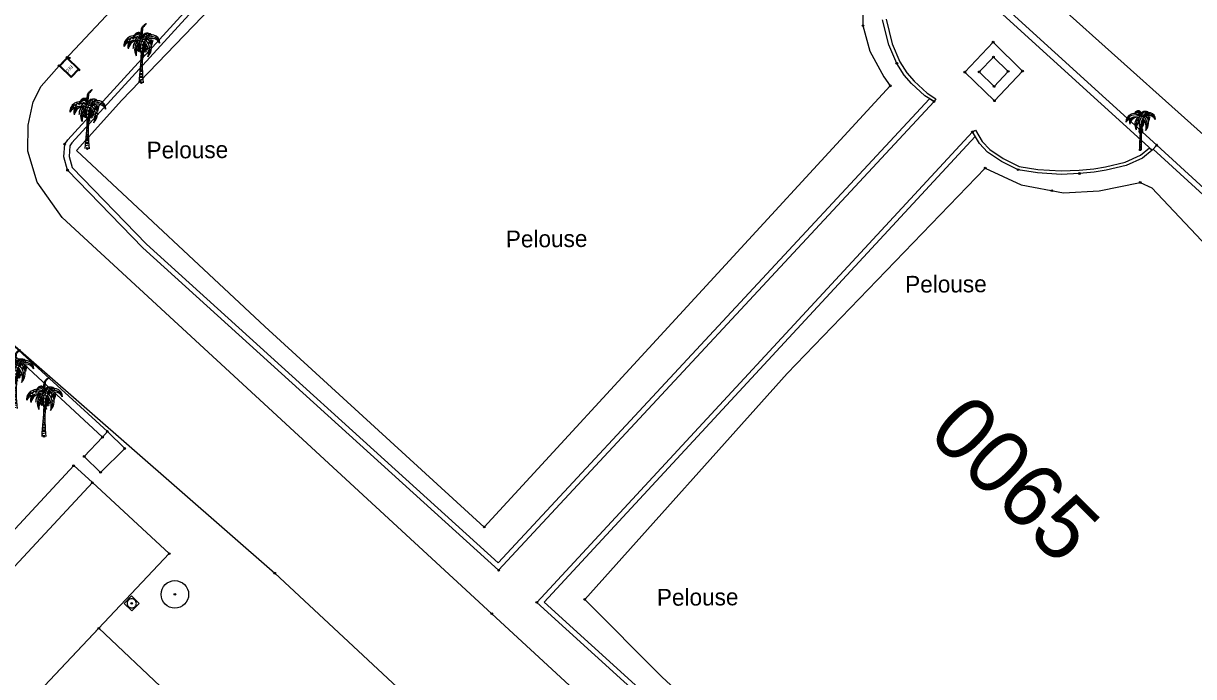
# Model space of a CAD drawing. Extents: x 344013 to 344423, y 298505 to 298795.
# Drawn here: x 344064.6 to 344132.3, y 298653.3 to 298691.1 of the extents above; entities that cross this region are included whole.
import ezdxf

# ---------------------------------------------------------------- set-up
doc = ezdxf.new("R2010")
doc.units = 0
for name, color, linetype in [('Default', 7, 'Continuous'), ('DH_CADRE -CARTOUCHE', 7, 'Continuous'), ('PC_CONCRETE', 7, 'Continuous'), ('PS_BOLT', 7, 'Continuous'), ('PS_CONST', 7, 'Continuous'), ('PS_HIDDEN', 7, 'Continuous'), ('RES_ELECTRICITE', 7, 'Continuous'), ('TOPO_POINT', 7, 'Continuous'), ('VOIRIE_BORDURE', 7, 'Continuous'), ('VOIRIE_ESPACE VERT', 7, 'Continuous')]:
    doc.layers.add(name, color=color, linetype=linetype)

# ---------------------------------------------------------------- blocks, each defined once
blk = doc.blocks.new('REG_INC')
at = {"layer": 'Default'}
for p, q in [((0, 1), (1, 1)), ((0, 0), (0, 1)), ((1, 0), (0, 0)), ((1, 1), (1, 0))]:
    blk.add_line(p, q, dxfattribs=at)
for start, end in [(135.0055, 180.0055), (180.0066, 225.0066), (90.0058, 135.0058), (225.0069, 270.0069), (45.0069, 90.0069), (270.0058, 315.0058), (0.0066, 45.0066), (315.0055, 0.0055)]:
    blk.add_arc((0.5, 0.5), 0.44, start, end, dxfattribs=at)
blk = doc.blocks.new('RES_ELECTRICITE')
at = {"layer": 'RES_ELECTRICITE'}
for points in [[(0, 0), (0, 1), (1, 1), (1, 0)], [(0.05, 0.05), (0.05, 0.95), (0.95, 0.95), (0.95, 0.05)]]:
    blk.add_lwpolyline(points, close=True, dxfattribs=at)
blk.add_text('EEC', height=0.2, dxfattribs=at).set_placement((0.237, 0.46))
blk = doc.blocks.new('POINT_DISPLAY')
at = {"layer": 'Default'}
blk.add_circle((0, 0), 0.05, dxfattribs=at)
blk = doc.blocks.new('COCO')
at = {"layer": 'Default'}
for p, q in [((-0.046, 0.891), (0.052, 0.927)), ((0.054, 0.998), (-0.041, 0.985)), ((-0.037, 1.06), (0.056, 1.071)), ((0.058, 1.14), (-0.03, 1.162)), ((-0.026, 1.226), (0.061, 1.212)), ((0.046, 0.033), (-0.076, 0.051)), ((-0.073, 0.17), (0.045, 0.209)), ((0.045, 0.292), (-0.07, 0.288)), ((-0.068, 0.371), (0.045, 0.374)), ((0.045, 0.47), (-0.065, 0.453)), ((-0.062, 0.537), (0.046, 0.552)), ((0.047, 0.655), (-0.058, 0.642))]:
    blk.add_line(p, q, dxfattribs=at)
for points in [[(0.029, 2.551), (-0.016, 2.896), (0.002, 3.125), (0.059, 3.241), (0.173, 3.348), (0.189, 3.356), (0.282, 3.415), (0.266, 3.373), (0.2, 3.318), (0.143, 3.247), (0.093, 3.2), (0.081, 3.165), (0.057, 3.133), (0.057, 3.099), (0.06, 3.037), (0.039, 2.989), (0.039, 2.944), (0.049, 2.877), (0.037, 2.841), (0.013, 2.736)], [(0.013, 2.736), (0.036, 2.813), (0.046, 2.746)], [(0.196, 2.687), (0.323, 2.715)], [(0.283, 2.765), (0.331, 2.786)], [(-0.746, 2.559), (-0.864, 2.483)], [(-0.77, 2.413), (-0.836, 2.333)], [(-0.607, 2.534), (-0.704, 2.443)], [(-0.636, 2.639), (-0.541, 2.608)], [(-0.421, 2.58), (-0.503, 2.523)], [(-0.487, 2.68), (-0.386, 2.65)], [(-0.183, 2.493), (-0.348, 2.417), (-0.401, 2.307), (-0.448, 2.203), (-0.471, 2.086), (-0.474, 2.023), (-0.466, 1.973), (-0.455, 2.054), (-0.451, 2.146), (-0.387, 2.292), (-0.351, 2.354), (-0.284, 2.404), (-0.233, 2.445), (-0.012, 2.495)], [(-0.256, 2.553), (-0.385, 2.508)], [(-0.276, 2.151), (-0.329, 2.086)], [(-0.203, 2.314), (-0.274, 2.258)], [(-0.23, 2.152), (-0.237, 2.043)], [(-0.161, 2.218), (-0.158, 2.122)], [(-0.04, 2.247), (-0.081, 2.179)], [(0.015, 2.414), (-0.056, 2.352)], [(-0.025, 2.032), (0.002, 1.954)], [(0.022, 2.24), (0.043, 2.13)], [(0.081, 2.404), (0.106, 2.299)], [(0.133, 2.608), (0.185, 2.634)], [(0.385, 2.37), (0.469, 2.254)], [(0.473, 2.115), (0.509, 2.012)], [(-0.321, 1.997), (-0.364, 1.9)], [(-0.059, 2.024), (-0.083, 1.998)], [(-0.055, 0.716), (0.048, 0.717), (0.049, 0.787), (-0.051, 0.795)]]:
    blk.add_lwpolyline(points, dxfattribs=at)
for centre, radius in [((-0.144, 1.978), 0.0616), ((-0.187, 1.897), 0.0384), ((-0.124, 1.896), 0.0376), ((-0.11, 1.84), 0.0471), ((0.134, 1.862), 0.0549), ((0.208, 1.822), 0.0626), ((0.254, 1.938), 0.0628)]:
    blk.add_circle(centre, radius, dxfattribs=at)
for centre, radius, start, end in [((-0.427, 2.113), 0.595, 43.61211, 181.46245), ((-0.123, 2.59), 0.323, 122.34745, 158.76357), ((-0.199, 2.618), 0.238, 4.52184, 154.10099), ((-0.252, 2.556), 0.231, 4.24411, 134.21032), ((-0.16, 2.647), 0.255, 21.08609, 122.34745), ((0.376, 2.508), 0.372, 113.76809, 175.33093), ((0.376, 2.508), 0.372, 113.76809, 175.33093), ((0.418, 2.527), 0.326, 97.12484, 183.95116), ((1.025, 2.053), 0.958, 126.68582, 153.16638), ((0.618, 2.316), 0.451, 356.16265, 159.00089), ((0.344, 2.407), 0.451, 69.08173, 104.86204), ((-1.005, 1.577), 1.786, 37.56679, 40.51564), ((-0.254, 2.28), 0.869, 28.47252, 37.09653), ((0.493, 2.767), 0.0679, 35.32051, 126.68582), ((-0.054, 2.379), 0.738, 25.81944, 35.32051), ((-0.291, 1.543), 0.918, 76.73894, 142.80251), ((-0.38, 1.964), 0.648, 57.91917, 166.62012), ((-0.3, 2.12), 0.482, 151.13313, 199.59422), ((-0.196, 1.874), 0.565, 78.51401, 171.35044), ((-0.32, 2.055), 0.433, 119.08336, 188.76207), ((0.362, 1.922), 0.754, 136.71129, 208.82208), ((0.551, 1.79), 0.879, 137.73301, 194.37159), ((0.649, 1.599), 0.949, 145.51456, 182.45279), ((0.62, 2.159), 0.753, 153.08677, 230.11243), ((0.659, 2.068), 0.718, 142.35537, 222.27942), ((-0.007, 2.465), 0.0563, 81.74752, 144.30354), ((-0.189, 1.21), 1.324, 71.37146, 81.74752), ((0.294, 2.595), 0.256, 198.67654, 199.76266), ((0.963, 1.939), 0.9, 143.98655, 203.42885), ((0.544, 1.816), 0.474, 137.19533, 172.89867), ((0.308, 2.014), 0.226, 121.42967, 182.28997), ((27.302, 0.106), 27.266, 175.47911, 176.55971), ((0.311, 2.152), 0.219, 141.85595, 191.51747), ((0.372, 1.847), 0.277, 133.59561, 173.48701), ((0.242, 1.964), 0.147, 110.97274, 165.97557), ((0.404, 1.878), 0.354, 125.05854, 146.38926), ((0.398, 2.098), 0.301, 136.45687, 162.06855), ((0.357, 2.084), 0.244, 133.11836, 172.75341), ((-0.759, 1.958), 0.922, 344.85055, 15.89877), ((-0.404, 2.045), 0.619, 329.46655, 26.67931), ((-0.289, 2.11), 0.564, 317.8279, 12.33856), ((0.59, 2.015), 0.548, 29.56544, 139.35171), ((-0.543, 1.744), 0.96, 344.8781, 41.14605), ((-0.341, 1.9), 0.828, 46.97669, 50.12313), ((0.609, 2.187), 0.468, 12.10772, 148.31459), ((-0.157, 2.027), 0.74, 51.24751, 54.5217), ((-0.341, 1.9), 0.828, 334.06866, 41.194), ((-0.157, 2.027), 0.74, 315.14717, 39.02392), ((-1.704, 1.849), 2.327, 7.59784, 16.36658), ((-0.254, 2.28), 0.869, 350.88829, 14.70633), ((-0.482, 2.552), 1.161, 339.35966, 356.59253), ((-85.428, 7.294), 85.622, 355.11326, 356.26352), ((-0.279, 1.637), 0.281, 2.14987, 36.63246), ((-0.265, 1.505), 0.316, 339.99973, 25.72283), ((0.199, 1.66), 0.176, 166.9443, 185.59662), ((0.808, 1.542), 0.777, 142.23578, 156.28002)]:
    blk.add_arc(centre, radius, start, end, dxfattribs=at)
blk.add_ellipse((27.425, 0.272), major_axis=(-27.371, 0.966), ratio=0.529859, start_param=6.255729, end_param=6.369141, dxfattribs=at)
blk = doc.blocks.new('PALMIER')
at = {"layer": 'Default'}
for p, q in [((0.066, 0.879), (-0.031, 0.865)), ((-0.027, 0.942), (0.068, 0.953)), ((0.07, 1.023), (-0.02, 1.046)), ((-0.016, 1.111), (0.072, 1.097)), ((-0.062, 0.035), (0.058, 0.076)), ((0.058, 0.159), (-0.059, 0.156)), ((-0.057, 0.24), (0.058, 0.243)), ((0.058, 0.341), (-0.054, 0.323)), ((-0.051, 0.409), (0.059, 0.425)), ((0.06, 0.53), (-0.047, 0.516)), ((-0.036, 0.77), (0.064, 0.807))]:
    blk.add_line(p, q, dxfattribs=at)
blk.add_lwpolyline([(-0.044, 0.591), (0.061, 0.593), (0.062, 0.664), (-0.041, 0.672)], dxfattribs=at)
for centre, radius, start, end in [((-0.427, 2.014), 0.606, 43.75383, 181.60417), ((-0.119, 2.5), 0.329, 122.48917, 158.90528), ((-0.196, 2.528), 0.242, 4.66355, 154.2427), ((-0.249, 2.465), 0.236, 4.38583, 134.35204), ((-0.156, 2.558), 0.26, 21.2278, 122.48917), ((0.39, 2.418), 0.379, 113.90981, 175.47265), ((0.39, 2.418), 0.379, 113.90981, 175.47265), ((0.433, 2.437), 0.332, 97.26656, 184.09287), ((1.052, 1.956), 0.976, 126.82753, 153.3081), ((0.636, 2.223), 0.459, 356.30437, 159.14261), ((0.629, 2.092), 0.477, 12.24944, 148.4563), ((0.357, 2.315), 0.459, 69.22345, 105.00376), ((-0.152, 1.926), 0.754, 51.38923, 54.66342), ((-1.014, 1.466), 1.819, 37.7085, 40.65735), ((-0.251, 2.185), 0.885, 28.61423, 37.23825), ((0.508, 2.682), 0.0691, 35.46223, 126.82753), ((-0.048, 2.285), 0.752, 25.96116, 35.46223), ((-0.287, 1.433), 0.935, 76.88066, 142.94423), ((-0.379, 1.861), 0.66, 58.06089, 166.76184), ((-0.298, 2.021), 0.491, 151.27485, 199.73594), ((-0.191, 1.77), 0.575, 78.65572, 171.49215), ((-0.318, 1.955), 0.441, 119.22507, 188.90379), ((0.377, 1.821), 0.768, 136.85301, 208.9638), ((0.57, 1.687), 0.895, 137.87473, 194.5133), ((0.671, 1.493), 0.966, 145.65628, 182.59451), ((0.64, 2.063), 0.767, 153.22849, 230.25415), ((0.679, 1.97), 0.731, 142.49709, 222.42113), ((0, 2.373), 0.0573, 81.88924, 144.44525), ((-0.275, 1.529), 0.286, 2.29159, 36.77418), ((-0.182, 1.095), 1.349, 71.51318, 81.88924), ((0.306, 2.506), 0.261, 198.81826, 199.90438), ((0.989, 1.84), 0.917, 144.12827, 203.57056), ((0.563, 1.714), 0.483, 137.33705, 173.04039), ((0.322, 1.915), 0.23, 121.57139, 182.43168), ((27.823, 0.039), 27.774, 175.62083, 176.70143), ((0.325, 2.055), 0.223, 141.99767, 191.65918), ((0.388, 1.745), 0.282, 133.73732, 173.62872), ((0.832, 1.435), 0.791, 142.37749, 156.42174), ((0.255, 1.864), 0.149, 111.11446, 166.11729), ((0.42, 1.776), 0.361, 125.20026, 146.53098), ((0.414, 2.001), 0.306, 136.59859, 162.21026), ((0.372, 1.986), 0.249, 133.26007, 172.89513), ((-0.764, 1.855), 0.939, 344.99226, 16.04048), ((-0.403, 1.944), 0.63, 329.60827, 26.82103), ((-0.287, 2.01), 0.575, 317.96962, 12.48027), ((0.609, 1.916), 0.559, 29.70715, 139.49343), ((-0.544, 1.637), 0.978, 345.01981, 41.28777), ((-0.338, 1.796), 0.844, 47.11841, 50.26484), ((-0.338, 1.796), 0.844, 334.21038, 41.33572), ((-0.152, 1.926), 0.754, 315.28888, 39.16564), ((-1.727, 1.741), 2.37, 7.73955, 16.5083), ((-0.251, 2.185), 0.885, 351.03001, 14.84805), ((-0.484, 2.461), 1.182, 339.50138, 356.73425), ((-0.205, 1.197), 0.169, 353.50598, 55.12107), ((-0.285, 1.344), 0.284, 348.96741, 47.50384), ((-0.721, 1.091), 0.712, 9.15549, 26.66867), ((-0.349, 1.239), 0.371, 353.62318, 41.34943), ((24.236, -0.46), 24.303, 175.11756, 178.94339), ((-0.586, 1.323), 0.604, 357.22259, 24.49773), ((0.287, 1.204), 0.266, 120.40763, 191.54922), ((-0.26, 1.395), 0.322, 340.14145, 25.86455), ((0.212, 1.553), 0.18, 167.08602, 185.73834), ((0.343, 1.162), 0.295, 120.97799, 179.22943), ((27.948, 0.208), 27.89, 177.28613, 180.41366), ((0.244, 1.306), 0.167, 110.73571, 185.35669), ((0.507, 1.019), 0.45, 131.01759, 160.16859)]:
    blk.add_arc(centre, radius, start, end, dxfattribs=at)

msp = doc.modelspace()

# ---------------------------------------------------------------- linework, layer by layer
at = {"layer": 'DH_CADRE -CARTOUCHE'}
for points in [[(344115.32, 298696.96), (344115.589, 298697.255), (344130.117, 298684.033), (344129.848, 298683.737)], [(344129.848, 298683.737), (344129.29, 298683.281), (344128.353, 298682.867), (344127.202, 298682.582), (344126.5, 298682.465), (344125.648, 298682.397), (344124.59, 298682.342), (344123.219, 298682.428), (344122.112, 298682.617), (344121.145, 298683.081), (344120.339, 298683.63), (344119.861, 298684.132), (344119.467, 298684.803), (344119.64, 298684.904), (344120.022, 298684.253), (344120.469, 298683.784), (344121.245, 298683.254), (344122.173, 298682.809), (344123.242, 298682.627), (344124.591, 298682.542), (344125.635, 298682.597), (344126.475, 298682.664), (344127.162, 298682.778), (344128.288, 298683.056), (344129.184, 298683.452), (344129.698, 298683.873)], [(344050.263, 298661.981), (344060.039, 298672.492), (344055.614, 298676.601), (344042.396, 298662.623), (344059.801, 298646.434), (344073.019, 298660.413), (344068.567, 298664.519), (344058.811, 298654.03)]]:
    msp.add_lwpolyline(points, close=True, dxfattribs=at)
msp.add_lwpolyline([(344114.467, 298691.322), (344114.82, 298689.897), (344115.266, 298688.858), (344115.671, 298688.21), (344116.089, 298687.743), (344116.837, 298687.038), (344117.346, 298686.721), (344117.24, 298686.552), (344116.714, 298686.878), (344115.945, 298687.603), (344115.51, 298688.09), (344115.088, 298688.765), (344114.63, 298689.833), (344114.27, 298691.284)], dxfattribs=at)
at = {"layer": 'PS_BOLT'}
for points in [[(344119.026, 298688.255), (344120.735, 298686.6), (344122.356, 298688.316), (344120.662, 298689.995)], [(344120.676, 298689.131), (344119.853, 298688.272), (344120.715, 298687.431), (344121.526, 298688.303)], [(344062.722, 298673.608), (344062.468, 298673.339), (344069.15, 298667.15), (344069.435, 298667.48)], [(344059.801, 298646.434), (344058.46, 298644.956), (344062.597, 298641.269), (344072.85, 298652.396), (344068.937, 298656.096)]]:
    msp.add_lwpolyline(points, close=True, dxfattribs=at)
msp.add_lwpolyline([(344069.435, 298667.48), (344070.439, 298666.494), (344069.043, 298665.113), (344068.097, 298666.035), (344069.15, 298667.15), (344069.435, 298667.48)], dxfattribs=at)
msp.add_circle((344073.341, 298658.058), 0.796, dxfattribs=at)
at = {"layer": 'PS_HIDDEN'}
msp.add_lwpolyline([(344060.039, 298672.492), (344050.263, 298661.981), (344058.811, 298654.03), (344068.567, 298664.519), (344067.505, 298665.507), (344058.737, 298656.08), (344052.312, 298662.055), (344061.101, 298671.505)], close=True, dxfattribs=at)
at = {"layer": 'VOIRIE_BORDURE'}
for points in [[(344135.602, 298647.623), (344124.992, 298635.682), (344123.722, 298634.656), (344121.833, 298633.77), (344119.792, 298633.516), (344117.727, 298633.77), (344116.3, 298634.425), (344115.03, 298635.389), (344091.665, 298656.941), (344066.817, 298679.859), (344065.379, 298681.895), (344064.833, 298683.692), (344064.865, 298685.2), (344065.154, 298686.548), (344065.609, 298687.44), (344066.641, 298688.625), (344090.832, 298714.382)], [(344012.906, 298712.566), (344019.297, 298706.391), (344032.494, 298694.078), (344035.262, 298691.929), (344038.684, 298689.77), (344042.541, 298687.653), (344055.386, 298681.278), (344062.722, 298673.608), (344079.116, 298659.278), (344094.724, 298644.749), (344120.412, 298621.951), (344137.791, 298639.981)], [(344124.372, 298692.186), (344148.812, 298670.333)]]:
    msp.add_lwpolyline(points, dxfattribs=at)
at = {"layer": 'VOIRIE_ESPACE VERT'}
for points in [[(344115.386, 298697.034), (344095.685, 298715.142), (344067.379, 298684.161), (344067.261, 298683.991), (344067.218, 298683.388), (344067.403, 298682.745), (344071.702, 298678.318), (344092.045, 298659.877), (344116.981, 298686.713), (344117.24, 298686.552), (344092.063, 298659.455), (344071.494, 298678.102), (344067.135, 298682.59), (344066.915, 298683.356), (344066.967, 298684.094), (344067.145, 298684.349), (344095.667, 298715.566), (344115.589, 298697.255)], [(344129.915, 298683.811), (344149.954, 298665.484), (344120.649, 298634.816), (344119.758, 298634.843), (344094.693, 298657.614), (344119.626, 298684.533), (344119.467, 298684.803), (344094.267, 298657.595), (344119.638, 298634.546), (344120.774, 298634.512), (344150.383, 298665.499), (344130.117, 298684.033)]]:
    msp.add_lwpolyline(points, close=True, dxfattribs=at)
for points in [[(344091.233, 298661.951), (344078.543, 298673.539), (344067.651, 298683.727), (344070.267, 298686.633), (344094.013, 298711.291), (344094.723, 298711.636), (344095.462, 298711.65), (344096.516, 298711.35), (344098.055, 298710.152), (344102.625, 298705.772), (344106.459, 298702.051), (344111.683, 298696.937), (344113.434, 298695.237), (344113.122, 298693.176), (344113.133, 298690.945), (344113.53, 298689.467), (344114.335, 298687.988), (344114.712, 298687.466), (344091.233, 298661.951)], [(344097.038, 298657.765), (344108.757, 298670.826), (344120.202, 298682.712), (344122.289, 298681.737), (344124.72, 298681.269), (344126.782, 298681.391), (344129.166, 298681.878), (344129.834, 298681.573), (344134.972, 298676.138)], [(344132.496, 298649.404), (344131.323, 298648.36), (344130.418, 298648.385), (344129.521, 298648.088), (344128.929, 298647.247), (344129.046, 298646.357), (344128.58, 298645.532), (344127.265, 298644.456), (344126.557, 298644.694), (344125.698, 298643.931), (344125.499, 298642.901), (344124.663, 298641.644), (344123.173, 298640.08), (344121.715, 298638.486), (344120.611, 298637.277), (344119.699, 298636.759), (344118.394, 298637.704), (344114.121, 298641.565), (344110.576, 298644.947), (344101.52, 298653.263), (344097.038, 298657.765)]]:
    msp.add_lwpolyline(points, dxfattribs=at)

# ---------------------------------------------------------------- block references
at = {"layer": 'PC_CONCRETE', "xscale": 0.604402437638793, "yscale": 0.6128218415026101, "rotation": 45.55520999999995}
msp.add_blockref('REG_INC', (344070.852, 298657.107), dxfattribs=at)
at = {"layer": 'RES_ELECTRICITE', "xscale": 0.6682002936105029, "yscale": 0.9825932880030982, "rotation": -134.09487000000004}
msp.add_blockref('RES_ELECTRICITE', (344067.106, 298689.104), dxfattribs=at)
at = {"layer": 'TOPO_POINT'}
for p in [(344113.133, 298690.945), (344120.662, 298689.995), (344067.106, 298689.104), (344067.235, 298689.078), (344115.088, 298688.765), (344120.676, 298689.131), (344066.641, 298688.625), (344067.781, 298688.39), (344119.026, 298688.255), (344119.853, 298688.272), (344121.526, 298688.303), (344122.356, 298688.316), (344071.402, 298687.647), (344114.712, 298687.466), (344120.715, 298687.431), (344117.24, 298686.552), (344120.735, 298686.6), (344119.467, 298684.803), (344066.967, 298684.094), (344130.117, 298684.033), (344068.279, 298683.837), (344129.167, 298683.768), (344120.202, 298682.712), (344067.135, 298682.59), (344122.112, 298682.617), (344125.648, 298682.397), (344124.055, 298681.4), (344129.166, 298681.878), (344065.774, 298667.192), (344069.15, 298667.15), (344069.435, 298667.48), (344070.439, 298666.494), (344068.097, 298666.035), (344067.484, 298665.495), (344069.043, 298665.113), (344068.567, 298664.519), (344091.233, 298661.951), (344073.019, 298660.413), (344079.116, 298659.278), (344092.063, 298659.455), (344073.341, 298658.058), (344097.038, 298657.765), (344070.844, 298657.537), (344094.267, 298657.595), (344091.665, 298656.941), (344068.937, 298656.096)]:
    msp.add_blockref('POINT_DISPLAY', p, dxfattribs=at)
at = {"layer": 'VOIRIE_ESPACE VERT'}
for p in [(344071.402, 298687.647), (344068.279, 298683.837), (344064.109, 298668.81), (344065.774, 298667.192)]:
    msp.add_blockref('COCO', p, dxfattribs=at)
at = {"layer": 'VOIRIE_ESPACE VERT', "xscale": 0.8, "yscale": 0.8000000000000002}
msp.add_blockref('PALMIER', (344129.167, 298683.768), dxfattribs=at)

# ---------------------------------------------------------------- texts
at = {"layer": 'PS_CONST'}
for s, height, rotation, p in [('Pelouse', 0.9758, 0.36652, (344071.71, 298683.26)), ('Pelouse', 0.9758, 0.36652, (344092.483, 298678.118)), ('Pelouse', 0.9758, 0.36652, (344115.574, 298675.5)), ('0065', 3.662, 315.36651, (344116.782, 298667.277)), ('Pelouse', 0.9758, 0.36652, (344101.218, 298657.396))]:
    msp.add_text(s, height=height, rotation=rotation, dxfattribs=at).set_placement(p)

doc.saveas('drawing.dxf')
